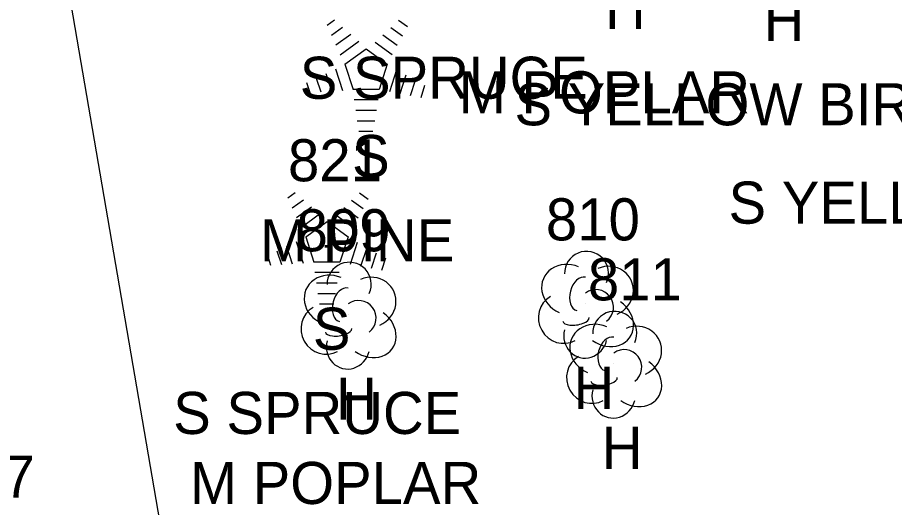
# Model space of a CAD drawing. Extents: x 1545627 to 1546562, y 571176 to 576667.
# Drawn here: x 1546125.89 to 1546167.52, y 572253.69 to 572276.96 of the extents above; entities that cross this region are included whole.
import ezdxf

# ---------------------------------------------------------------- set-up
doc = ezdxf.new("R2010")
doc.units = 0
for name, color, linetype in [('L_A', 7, 'Continuous'), ('L_C', 7, 'Continuous'), ('L_I', 7, 'Continuous'), ('LELB', 7, 'Continuous'), ('LTC', 7, 'Continuous'), ('LTD', 7, 'Continuous')]:
    doc.layers.add(name, color=color, linetype=linetype)

msp = doc.modelspace()

# ---------------------------------------------------------------- linework, layer by layer
at = {"layer": 'LELB'}
msp.add_lwpolyline([(1546138.092, 572206.647), (1546133.659, 572247.148), (1546122.485, 572312.188), (1546113.316, 572377.356), (1546104.81, 572426.631), (1546099.996, 572460.654), (1546092.988, 572497.654), (1546081.836, 572529.538), (1546071.729, 572550.604), (1546058.937, 572584.302), (1546058.009, 572591.614), (1546041.849, 572621.011), (1546036.285, 572644.955)], dxfattribs=at)
at = {"layer": 'LTC'}
for p, q in [((1546140.585, 572276.587), (1546140.939, 572276.844)), ((1546143.983, 572276.827), (1546144.402, 572276.523)), ((1546140.794, 572276.122), (1546141.324, 572276.506)), ((1546143.612, 572276.479), (1546144.162, 572276.08)), ((1546141.004, 572275.656), (1546141.708, 572276.167)), ((1546141.214, 572275.19), (1546142.092, 572275.828)), ((1546142.87, 572275.782), (1546143.679, 572275.194)), ((1546143.241, 572276.131), (1546143.92, 572275.637)), ((1546141.438, 572274.735), (1546142.45, 572275.469)), ((1546142.45, 572275.469), (1546143.447, 572274.744)), ((1546141.438, 572274.735), (1546141.825, 572273.542)), ((1546143.447, 572274.744), (1546143.056, 572273.542)), ((1546140.528, 572274.299), (1546140.799, 572273.464)), ((1546140.984, 572274.516), (1546141.314, 572273.497)), ((1546143.884, 572274.474), (1546143.547, 572273.434)), ((1546144.329, 572274.223), (1546144.042, 572273.339)), ((1546139.617, 572273.866), (1546139.769, 572273.398)), ((1546140.073, 572274.083), (1546140.284, 572273.431)), ((1546144.774, 572273.973), (1546144.537, 572273.244)), ((1546145.218, 572273.723), (1546145.031, 572273.149)), ((1546143.056, 572273.542), (1546141.825, 572273.542)), ((1546143.017, 572273.042), (1546141.873, 572273.042)), ((1546142.934, 572272.542), (1546141.945, 572272.542)), ((1546142.85, 572272.042), (1546142.018, 572272.042)), ((1546142.766, 572271.542), (1546142.091, 572271.542)), ((1546138.722, 572268.388), (1546139.077, 572268.645)), ((1546138.932, 572267.922), (1546139.461, 572268.306)), ((1546141.749, 572268.28), (1546142.299, 572267.881)), ((1546142.121, 572268.628), (1546142.54, 572268.323)), ((1546139.142, 572267.456), (1546139.845, 572267.968)), ((1546141.379, 572267.931), (1546142.058, 572267.438)), ((1546139.351, 572266.991), (1546140.229, 572267.628)), ((1546141.007, 572267.583), (1546141.817, 572266.994)), ((1546139.576, 572266.536), (1546140.587, 572267.27)), ((1546140.587, 572267.27), (1546141.584, 572266.545)), ((1546139.121, 572266.316), (1546139.452, 572265.297)), ((1546139.576, 572266.536), (1546139.963, 572265.342)), ((1546141.584, 572266.545), (1546141.193, 572265.342)), ((1546142.022, 572266.274), (1546141.684, 572265.235)), ((1546138.21, 572265.883), (1546138.422, 572265.232)), ((1546138.666, 572266.1), (1546138.937, 572265.265)), ((1546142.467, 572266.024), (1546142.179, 572265.139)), ((1546137.755, 572265.667), (1546137.907, 572265.199)), ((1546142.911, 572265.774), (1546142.674, 572265.044)), ((1546143.355, 572265.523), (1546143.169, 572264.949)), ((1546141.193, 572265.342), (1546139.963, 572265.342)), ((1546141.155, 572264.842), (1546140.01, 572264.842)), ((1546141.071, 572264.342), (1546140.083, 572264.342)), ((1546140.987, 572263.842), (1546140.156, 572263.842)), ((1546140.904, 572263.342), (1546140.229, 572263.342))]:
    msp.add_line(p, q, dxfattribs=at)
at = {"layer": 'LTD'}
for p, q in [((1546152.856, 572263.372), (1546152.856, 572263.372)), ((1546152.856, 572263.372), (1546152.856, 572263.372)), ((1546141.588, 572262.854), (1546141.588, 572262.854)), ((1546141.588, 572262.854), (1546141.588, 572262.854)), ((1546154.196, 572260.524), (1546154.196, 572260.524)), ((1546154.196, 572260.524), (1546154.196, 572260.524))]:
    msp.add_line(p, q, dxfattribs=at)
for centre in [(1546152.903, 572264.806), (1546141.635, 572264.288), (1546154.243, 572261.958)]:
    msp.add_arc(centre, 1.047, 335.5272, 180.9563, dxfattribs=at)
for centre, major_axis, ratio, start_param, end_param in [((1546152.064, 572264.038), (1.21, -0.512), 0.895232, 1.570796, 4.712389), ((1546153.898, 572263.955), (-1.141, -0.483), 0.949671, 1.570796, 4.712389), ((1546140.796, 572263.521), (1.21, -0.512), 0.895232, 1.570796, 4.712389), ((1546142.629, 572263.438), (-1.141, -0.483), 0.949671, 1.570796, 4.712389), ((1546152.648, 572263.83), (-0.208, -0.792), 0.645439, 3.141593, 6.283185), ((1546141.38, 572263.313), (-0.208, -0.792), 0.645439, 3.141593, 6.283185), ((1546153.356, 572263.205), (-0.5, 0.667), 0.989748, 3.141593, 6.283185), ((1546151.773, 572262.663), (0.584, -1.042), 0.959034, 3.141593, 6.283185), ((1546142.088, 572262.688), (-0.5, 0.667), 0.989748, 3.141593, 6.283185), ((1546153.856, 572262.539), (-1.09, 0.792), 0.841452, 1.570796, 4.712389), ((1546140.505, 572262.146), (0.584, -1.042), 0.959034, 3.141593, 6.283185), ((1546142.588, 572262.021), (-1.09, 0.792), 0.841452, 1.570796, 4.712389), ((1546152.398, 572262.622), (-0.625, -0.083), 0.423636, 0, 3.141593), ((1546153.404, 572261.19), (1.21, -0.512), 0.895232, 1.570796, 4.712389), ((1546155.238, 572261.107), (-1.141, -0.483), 0.949671, 1.570796, 4.712389), ((1546141.13, 572262.104), (-0.625, -0.083), 0.423636, 0, 3.141593), ((1546152.856, 572261.872), (0.265, 1.061), 0.942809, 1.570796, 4.712389), ((1546153.988, 572260.982), (-0.208, -0.792), 0.645439, 3.141593, 6.283185), ((1546141.588, 572261.354), (0.265, 1.061), 0.942809, 1.570796, 4.712389), ((1546154.696, 572260.357), (-0.5, 0.667), 0.989748, 3.141593, 6.283185), ((1546153.113, 572259.815), (0.584, -1.042), 0.959034, 3.141593, 6.283185), ((1546155.196, 572259.69), (-1.09, 0.792), 0.841452, 1.570796, 4.712389), ((1546153.738, 572259.773), (-0.625, -0.083), 0.423636, 0, 3.141593), ((1546154.196, 572259.024), (0.265, 1.061), 0.942809, 1.570796, 4.712389)]:
    msp.add_ellipse(centre, major_axis=major_axis, ratio=ratio, start_param=start_param, end_param=end_param, dxfattribs=at)

# ---------------------------------------------------------------- texts
at = {"layer": 'L_A'}
for s, p in [('H', (1546153.78, 572276.404)), ('H', (1546161.309, 572275.837)), ('S', (1546141.776, 572269.379)), ('S', (1546139.913, 572261.179)), ('H', (1546152.289, 572258.372)), ('H', (1546141.021, 572257.854)), ('H', (1546153.629, 572255.524))]:
    msp.add_text(s, height=2, dxfattribs=at).set_placement(p)
at = {"layer": 'L_C'}
for s, p in [('S SPRUCE', (1546139.292, 572273.096)), ('M POPLAR', (1546146.843, 572272.404)), ('S YELLOW BIRCH', (1546149.482, 572271.837)), ('S YELLOW BIRCH', (1546159.643, 572267.167)), ('M PINE', (1546137.413, 572265.379)), ('S SPRUCE', (1546133.283, 572257.179)), ('M POPLAR', (1546134.084, 572253.854))]:
    msp.add_text(s, height=2, dxfattribs=at).set_placement(p)
at = {"layer": 'L_I'}
for s, p in [('821', (1546138.732, 572269.179)), ('810', (1546150.974, 572266.372)), ('809', (1546139.139, 572265.854)), ('811', (1546152.968, 572263.524)), ('1337', (1546120.76, 572254.154))]:
    msp.add_text(s, height=2, dxfattribs=at).set_placement(p)
at = {"layer": 'LTC'}
for p in [(1546142.332, 572274.483), (1546140.47, 572266.283)]:
    msp.add_text('.', height=1.037, rotation=270, dxfattribs=at).set_placement(p)

doc.saveas('drawing.dxf')
